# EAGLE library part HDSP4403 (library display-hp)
LED DISPLAY 1-character dot matrix without decimal point
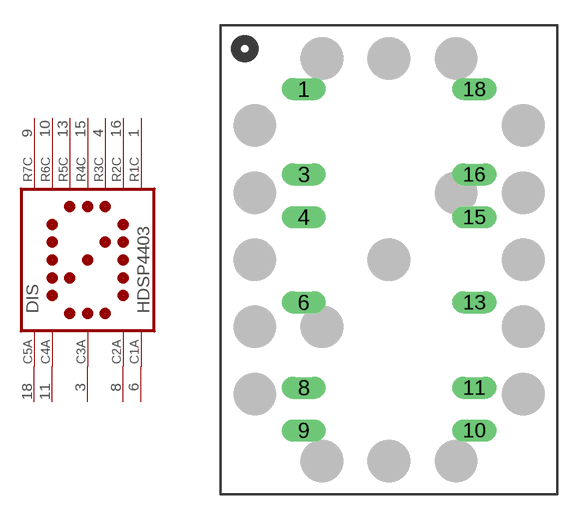
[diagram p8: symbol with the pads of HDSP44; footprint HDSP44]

Designator prefix DIS

## HDSP4403 (OC_FARNELL: unknown; OC_NEWARK: unknown)  [HDSP44]
1  R1C  pas
3  C3A  pas
4  R3C  pas
6  C1A  pas
8  C2A  pas
9  R7C  pas
10  R6C  pas
11  C4A  pas
13  R5C  pas
15  R4C  pas
16  R2C  pas
18  C5A  pas

## Footprint HDSP44 (pad centres in mm)
LED DISPLAY 27-mm 1 character dot matrix without decimal point
drill 0.813 long: 1 -5.08,10.16; 3 -5.08,5.08; 4 -5.08,2.54; 6 -5.08,-2.54; 8 -5.08,-7.62; 9 -5.08,-10.16; 10 5.08,-10.16; 11 5.08,-7.62; 13 5.08,-2.54; 15 5.08,2.54; 16 5.08,5.08; 18 5.08,10.16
